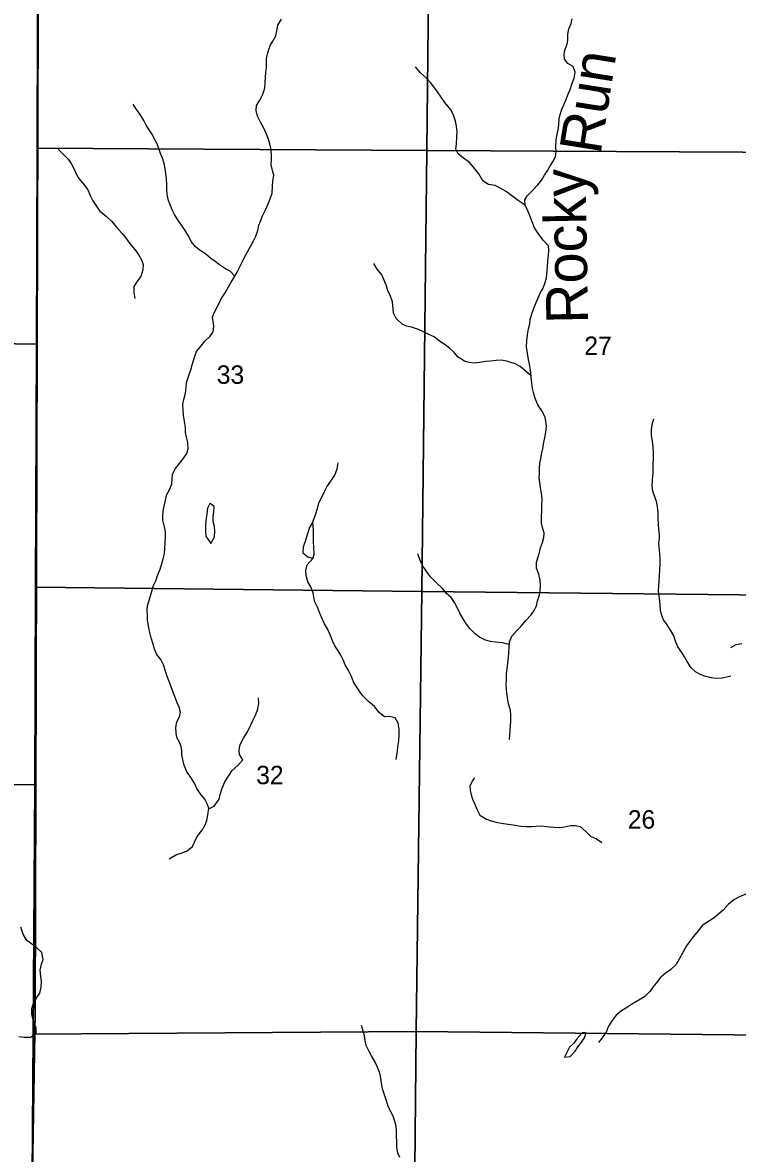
# Model space of a CAD drawing. Extents: x -10 to 158, y 8 to 33.
# Drawn here: x -7.945 to -6.322, y 10.614 to 13.18 of the extents above; entities that cross this region are included whole.
import ezdxf

# ---------------------------------------------------------------- set-up
doc = ezdxf.new("R2010")
doc.units = 0
for name, color, linetype in [('GM_X_Corporation', 7, 'Continuous'), ('GM_X_Minor_Lake', 7, 'Continuous'), ('GM_X_Minor_River', 7, 'Continuous'), ('GM_X_Minor_River_Text', 7, 'Continuous'), ('GM_X_Section_Text', 7, 'Continuous')]:
    doc.layers.add(name, color=color, linetype=linetype)

msp = doc.modelspace()

# ---------------------------------------------------------------- linework, layer by layer
at = {"layer": 'GM_X_Corporation'}
for points in [[(-7.9061, 15.1217), (-9.5644, 15.1217), (-9.5644, 9.4643), (-9.3995, 9.4613), (-9.0726, 9.4561), (-8.6489, 9.4603), (-8.2177, 9.4548), (-7.9405, 9.4552), (-7.9277, 10.2365), (-7.9276, 10.245), (-7.9163, 10.9333), (-7.9163, 10.9342), (-7.9089, 13.4536), (-7.9044, 14.3264), (-7.9061, 14.9432), (-7.9061, 14.9456)], [(-7.9093, 13.8977), (-7.016, 13.8932), (-7.0267, 12.8896), (-7.912, 12.8954), (-7.9104, 13.468)], [(-7.016, 13.8932), (-6.0166, 13.8862), (-6.0224, 12.8846), (-7.0267, 12.8896)], [(-7.9104, 13.468), (-7.912, 12.8954), (-7.9134, 12.4505), (-8.922, 12.4664), (-8.9211, 13.4645)], [(-7.0267, 12.8896), (-7.0382, 11.889), (-7.9152, 11.8987), (-7.9134, 12.4505), (-7.912, 12.8954)], [(-6.0224, 12.8846), (-6.0285, 11.878), (-7.0382, 11.889), (-7.0267, 12.8896)], [(-7.9134, 12.4505), (-7.9152, 11.8987), (-7.9172, 11.45), (-8.9234, 11.4538), (-8.922, 12.4664)], [(-7.0382, 11.889), (-7.0512, 10.8902), (-7.9205, 10.8845), (-7.9172, 11.45), (-7.9152, 11.8987)], [(-6.0285, 11.878), (-6.04, 10.88), (-7.0512, 10.8902), (-7.0382, 11.889)], [(-7.9172, 11.45), (-7.9205, 10.8845), (-7.9238, 10.4498), (-8.9307, 10.4584), (-8.9234, 11.4538)], [(-7.0512, 10.8902), (-7.0611, 9.881), (-7.9279, 9.893), (-7.9238, 10.4498), (-7.9205, 10.8845)], [(-6.04, 10.88), (-6.0536, 9.8669), (-7.0611, 9.881), (-7.0512, 10.8902)]]:
    msp.add_lwpolyline(points, close=True, dxfattribs=at)
msp.add_lwpolyline([(-3.9824, 15.1217), (-7.9061, 15.1217), (-7.9061, 14.9456), (-7.9061, 14.9432), (-7.9044, 14.3264), (-7.9089, 13.4536), (-7.9163, 10.9342), (-7.9163, 10.9333), (-7.9276, 10.245), (-7.9277, 10.2365), (-7.9405, 9.4552), (-7.9359, 8.9497), (-7.8105, 8.9446), (-6.576, 8.9279), (-5.6716, 8.9116)], dxfattribs=at)
at = {"layer": 'GM_X_Minor_Lake'}
for points in [[(-7.5158, 12.086), (-7.5194, 12.0884), (-7.525, 12.0782), (-7.5267, 12.0641), (-7.5289, 12.0508), (-7.5296, 12.0375), (-7.5295, 12.0247), (-7.5287, 12.0144), (-7.5176, 11.9982)], [(-7.5176, 11.9982), (-7.509, 12.013), (-7.5083, 12.0259), (-7.5091, 12.0365), (-7.5122, 12.0468), (-7.5123, 12.0566), (-7.5105, 12.0695), (-7.5098, 12.082), (-7.5158, 12.086)], [(-7.2856, 12.0471), (-7.2933, 12.0343), (-7.2997, 12.0155), (-7.3042, 12.0003), (-7.3079, 11.99), (-7.3085, 11.9768), (-7.2971, 11.9677), (-7.2854, 11.9636)], [(-7.2854, 11.9636), (-7.2824, 11.9739), (-7.2836, 11.9891), (-7.2845, 12.0027), (-7.2846, 12.016), (-7.2843, 12.0277), (-7.2847, 12.0372), (-7.2856, 12.0471)], [(-6.7144, 10.8323), (-6.7015, 10.8337), (-6.6899, 10.846), (-6.6836, 10.8559), (-6.6754, 10.8659), (-6.6691, 10.8758), (-6.6651, 10.8877), (-6.672, 10.8873)], [(-6.672, 10.8873), (-6.6745, 10.8872), (-6.6857, 10.8741), (-6.6928, 10.8641), (-6.7029, 10.8545), (-6.7144, 10.8323)]]:
    msp.add_lwpolyline(points, dxfattribs=at)
at = {"layer": 'GM_X_Minor_River'}
for points in [[(-7.519, 12.4685), (-7.5122, 12.4784), (-7.5104, 12.4913), (-7.5117, 12.5019), (-7.5136, 12.5113), (-7.5095, 12.5212), (-7.5043, 12.5315), (-7.498, 12.5456), (-7.492, 12.5551), (-7.4845, 12.5669), (-7.477, 12.5806), (-7.471, 12.5913), (-7.4628, 12.6042), (-7.4579, 12.6137), (-7.4523, 12.624), (-7.4479, 12.6335), (-7.4415, 12.6464), (-7.4344, 12.6598), (-7.4262, 12.6731), (-7.4206, 12.6849), (-7.4154, 12.6952), (-7.4109, 12.7085), (-7.408, 12.7202), (-7.4043, 12.7297), (-7.399, 12.7427), (-7.3931, 12.7552), (-7.3871, 12.7689), (-7.3827, 12.7799), (-7.3782, 12.7932), (-7.3776, 12.8092), (-7.3769, 12.8202), (-7.3743, 12.8335), (-7.3774, 12.8444), (-7.3802, 12.8573), (-7.3795, 12.8698), (-7.3796, 12.8805), (-7.3812, 12.8949), (-7.3831, 12.9047), (-7.3866, 12.9153), (-7.3912, 12.9267), (-7.397, 12.9403), (-7.4043, 12.9539), (-7.4112, 12.9675), (-7.4147, 12.9804), (-7.4133, 12.9917), (-7.4062, 13.0043), (-7.3991, 13.0176), (-7.3946, 13.0313), (-7.3936, 13.0435), (-7.3929, 13.0564), (-7.3922, 13.0658), (-7.3908, 13.0784), (-7.3912, 13.089), (-7.3906, 13.0988), (-7.3869, 13.1148), (-7.3828, 13.1281), (-7.3768, 13.1376), (-7.3697, 13.1502), (-7.3675, 13.1616), (-7.365, 13.1745), (-7.3567, 13.1878)], [(-6.8035, 12.7658), (-6.8047, 12.7776), (-6.7988, 12.7871), (-6.7871, 12.7989), (-6.7747, 12.8119), (-6.7657, 12.8233), (-6.7597, 12.834), (-6.7519, 12.8451), (-6.7466, 12.8546), (-6.7399, 12.8652), (-6.735, 12.8755), (-6.7332, 12.8876), (-6.7337, 12.899), (-6.7334, 12.9138), (-6.7312, 12.926), (-6.7283, 12.9404), (-6.7272, 12.9506), (-6.7262, 12.9617), (-6.7244, 12.9715), (-6.7203, 12.9837), (-6.7162, 12.9932), (-6.711, 13.0038), (-6.7058, 13.0175), (-6.7017, 13.0282), (-6.6976, 13.0403), (-6.6924, 13.054), (-6.6898, 13.0673), (-6.6948, 13.0806), (-6.707, 13.0869), (-6.7143, 13.0971), (-6.7151, 13.1074), (-6.7136, 13.1176), (-6.7081, 13.1309), (-6.707, 13.1404), (-6.7071, 13.1529), (-6.7045, 13.1662), (-6.6993, 13.178), (-6.6967, 13.1886)], [(-6.8035, 12.7658), (-6.8195, 12.7764), (-6.8343, 12.7876), (-6.8484, 12.7974), (-6.859, 12.8038), (-6.8716, 12.8102), (-6.8871, 12.8123), (-6.9, 12.8213), (-6.9085, 12.8365), (-6.9207, 12.8516), (-6.931, 12.8636), (-6.9435, 12.8726), (-6.9561, 12.8824), (-6.9607, 12.893), (-6.9597, 12.9044), (-6.9586, 12.9211), (-6.9583, 12.9321), (-6.9596, 12.945), (-6.9619, 12.9567), (-6.9673, 12.9722), (-6.9723, 12.9824), (-6.9857, 12.9987), (-7.0025, 13.0228), (-7.0109, 13.0342), (-7.0189, 13.044), (-7.0277, 13.0542), (-7.041, 13.0662), (-7.0525, 13.0794)], [(-7.4626, 12.6045), (-7.4727, 12.6155), (-7.486, 12.6226), (-7.4974, 12.6305), (-7.5073, 12.6381), (-7.5176, 12.6444), (-7.529, 12.6546), (-7.5423, 12.6636), (-7.5522, 12.6715), (-7.5621, 12.6836), (-7.5679, 12.6964), (-7.5771, 12.7104), (-7.5843, 12.7206), (-7.5939, 12.7346), (-7.6, 12.7444), (-7.605, 12.755), (-7.6089, 12.7652), (-7.6135, 12.7762), (-7.6166, 12.7898), (-7.6171, 12.8038), (-7.6171, 12.8137), (-7.618, 12.8255), (-7.6192, 12.8372), (-7.6208, 12.8478), (-7.6235, 12.8603), (-7.6274, 12.872), (-7.6316, 12.883), (-7.6351, 12.894), (-7.639, 12.9046), (-7.6451, 12.9152), (-7.6497, 12.925), (-7.6574, 12.9367), (-7.6643, 12.9469), (-7.6696, 12.9579), (-7.6777, 12.9718), (-7.688, 12.9851), (-7.6934, 12.9949)], [(-7.8641, 12.8929), (-7.8526, 12.8816), (-7.8412, 12.8699), (-7.8347, 12.8601), (-7.8282, 12.8488), (-7.8228, 12.8367), (-7.8174, 12.8261), (-7.8045, 12.811), (-7.7968, 12.8008), (-7.7903, 12.786), (-7.7849, 12.7758), (-7.7761, 12.7619), (-7.7692, 12.752), (-7.7548, 12.7404), (-7.7426, 12.7295), (-7.7304, 12.7151), (-7.7197, 12.7023), (-7.7109, 12.6921), (-7.7021, 12.6793), (-7.6899, 12.6653), (-7.6815, 12.6536), (-7.675, 12.6419), (-7.6711, 12.6313), (-7.6714, 12.6192), (-7.6766, 12.604), (-7.6841, 12.5941), (-7.6923, 12.5811), (-7.6919, 12.5675), (-7.6899, 12.5542)], [(-6.8391, 11.5531), (-6.8376, 11.5744), (-6.8369, 11.5839), (-6.8362, 11.5941), (-6.8359, 11.6089), (-6.8371, 11.6195), (-6.8418, 11.6339), (-6.843, 11.6434), (-6.845, 11.6581), (-6.8462, 11.6676), (-6.8466, 11.6782), (-6.8463, 11.6885), (-6.8457, 11.7029), (-6.8446, 11.7131), (-6.8428, 11.7253), (-6.8417, 11.7389), (-6.8407, 11.7499), (-6.84, 11.7617), (-6.8394, 11.7746), (-6.8341, 11.7872), (-6.8229, 11.8001), (-6.8135, 11.8097), (-6.8018, 11.823), (-6.7898, 11.8356), (-6.7831, 11.8459), (-6.7782, 11.8562), (-6.7753, 11.8676), (-6.772, 11.8782), (-6.7698, 11.8892), (-6.7691, 11.9032), (-6.7692, 11.9142), (-6.7727, 11.9283), (-6.7777, 11.9415), (-6.7778, 11.9544), (-6.7748, 11.965), (-6.7711, 11.9772), (-6.7689, 11.9878), (-6.7645, 12.0004), (-6.7615, 12.0114), (-6.7605, 12.0216), (-6.7643, 12.0345), (-6.7667, 12.0443), (-6.7664, 12.0572), (-6.7661, 12.0724), (-6.7655, 12.0849), (-6.7648, 12.0997), (-6.7668, 12.1115), (-6.7688, 12.1251), (-6.7704, 12.1365), (-6.7716, 12.146), (-6.7709, 12.1573), (-6.771, 12.1687), (-6.7703, 12.1809), (-6.7677, 12.1911), (-6.7655, 12.2036), (-6.7637, 12.2131), (-6.7619, 12.2238), (-6.7593, 12.2374), (-6.7568, 12.2507), (-6.755, 12.264), (-6.7566, 12.275), (-6.7581, 12.2845), (-6.7654, 12.2988), (-6.775, 12.3128), (-6.7808, 12.3268), (-6.7847, 12.3404), (-6.7866, 12.3499), (-6.7882, 12.362), (-6.7898, 12.3749), (-6.7906, 12.3851), (-6.7922, 12.3954), (-6.7938, 12.4052), (-6.7958, 12.4158), (-6.7985, 12.4298), (-6.8005, 12.4442), (-6.8002, 12.4583), (-6.7984, 12.4716), (-6.7959, 12.4852), (-6.7933, 12.4966), (-6.7919, 12.5061), (-6.7886, 12.5194), (-6.7841, 12.5316), (-6.7789, 12.5449), (-6.774, 12.5552), (-6.7692, 12.5658), (-6.7636, 12.5757), (-6.7591, 12.5882), (-6.7554, 12.6008), (-6.7537, 12.6163), (-6.7526, 12.6274), (-6.7519, 12.6387), (-6.7505, 12.6524), (-6.7498, 12.6626), (-6.751, 12.6733), (-6.7625, 12.6861), (-6.7736, 12.7008), (-6.7824, 12.7144), (-6.7877, 12.728), (-6.792, 12.7397), (-6.7974, 12.7526), (-6.8035, 12.7658)], [(-6.7901, 12.3785), (-6.8153, 12.3998), (-6.8264, 12.4054), (-6.8358, 12.4087), (-6.8453, 12.4117), (-6.8582, 12.4139), (-6.8696, 12.4131), (-6.882, 12.4119), (-6.8926, 12.411), (-6.9074, 12.4083), (-6.9191, 12.4071), (-6.9308, 12.4085), (-6.9415, 12.4119), (-6.9559, 12.4209), (-6.9647, 12.4311), (-6.975, 12.4401), (-6.9856, 12.4491), (-6.9982, 12.4574), (-7.01, 12.4672), (-7.0225, 12.4724), (-7.0331, 12.4773), (-7.046, 12.4832), (-7.0616, 12.4885), (-7.073, 12.4914), (-7.0832, 12.4955), (-7.0969, 12.5083), (-7.1027, 12.5208), (-7.1031, 12.5307), (-7.1048, 12.5466), (-7.1105, 12.5613), (-7.1151, 12.5715), (-7.1182, 12.5825), (-7.1244, 12.5973), (-7.1294, 12.6079), (-7.1397, 12.6207), (-7.1474, 12.6332)], [(-7.6122, 11.2825), (-7.5951, 11.2923), (-7.5846, 11.2954), (-7.571, 11.3), (-7.5593, 11.3103), (-7.5541, 11.3198), (-7.5481, 11.3328), (-7.5369, 11.3469), (-7.5305, 11.3594), (-7.5264, 11.3689), (-7.5239, 11.3822), (-7.5221, 11.397), (-7.5259, 11.4069), (-7.5313, 11.4174), (-7.5412, 11.4307), (-7.5489, 11.442), (-7.5543, 11.4537), (-7.5631, 11.4666), (-7.5726, 11.4813), (-7.578, 11.4945), (-7.58, 11.504), (-7.5831, 11.518), (-7.5832, 11.5275), (-7.5844, 11.537), (-7.5886, 11.5472), (-7.5943, 11.5574), (-7.5963, 11.5676), (-7.5968, 11.5805), (-7.5946, 11.5934), (-7.5886, 11.6048), (-7.5864, 11.6147), (-7.5895, 11.6264), (-7.5934, 11.6366), (-7.5988, 11.6503), (-7.6034, 11.662), (-7.6084, 11.6748), (-7.6123, 11.6847), (-7.6165, 11.696), (-7.62, 11.7078), (-7.625, 11.7225), (-7.6312, 11.7346), (-7.6396, 11.7459), (-7.645, 11.7577), (-7.6492, 11.7717), (-7.6531, 11.7834), (-7.6566, 11.7989), (-7.6586, 11.8107), (-7.6609, 11.8236), (-7.6614, 11.8342), (-7.6618, 11.8463), (-7.6608, 11.8562), (-7.6578, 11.8661), (-7.6549, 11.8767), (-7.6519, 11.887), (-7.6482, 11.901), (-7.6415, 11.9143), (-7.6382, 11.925), (-7.6326, 11.9398), (-7.6289, 11.9527), (-7.6256, 11.9634), (-7.6223, 11.9751), (-7.6216, 11.9858), (-7.6209, 11.9998), (-7.6199, 12.0131), (-7.62, 12.0248), (-7.6223, 12.0354), (-7.6262, 12.0506), (-7.6267, 12.0631), (-7.6248, 12.0756), (-7.6197, 12.0992), (-7.6171, 12.1094), (-7.6115, 12.1193), (-7.606, 12.1334), (-7.6053, 12.1448), (-7.6046, 12.1554), (-7.5975, 12.1683), (-7.5896, 12.1786), (-7.5784, 12.1923), (-7.572, 12.2019), (-7.5687, 12.2133), (-7.5695, 12.2273), (-7.5723, 12.239), (-7.5746, 12.2496), (-7.5751, 12.261), (-7.5774, 12.2747), (-7.5794, 12.2891), (-7.5803, 12.3004), (-7.5807, 12.3141), (-7.5789, 12.3243), (-7.5752, 12.3388), (-7.5734, 12.3509), (-7.5724, 12.3634), (-7.5672, 12.379), (-7.5631, 12.3919), (-7.5598, 12.4033), (-7.5568, 12.4128), (-7.5535, 12.4231), (-7.5498, 12.4334), (-7.5396, 12.4467), (-7.531, 12.4574), (-7.519, 12.4685)], [(-6.3363, 11.6965), (-6.343, 11.6955), (-6.3566, 11.6924), (-6.3706, 11.6911), (-6.3816, 11.693), (-6.3937, 11.6963), (-6.4059, 11.7008), (-6.4169, 11.7064), (-6.4268, 11.7154), (-6.4356, 11.7298), (-6.4421, 11.7404), (-6.4482, 11.7506), (-6.457, 11.763), (-6.462, 11.7763), (-6.4663, 11.788), (-6.474, 11.8008), (-6.4812, 11.8133), (-6.4896, 11.8246), (-6.4943, 11.8364), (-6.4962, 11.8462), (-6.4971, 11.8576), (-6.4979, 11.8678), (-6.4995, 11.8784), (-6.5011, 11.8898), (-6.5004, 11.9016), (-6.4993, 11.9133), (-6.4983, 11.9239), (-6.4976, 11.9387), (-6.4973, 11.9501), (-6.4974, 11.9638), (-6.4979, 11.9732), (-6.4983, 11.9835), (-6.4999, 11.9975), (-6.4985, 12.0097), (-6.4986, 12.0191), (-6.4998, 12.0297), (-6.5006, 12.0419), (-6.5015, 12.0555), (-6.5019, 12.0684), (-6.5028, 12.0817), (-6.5055, 12.093), (-6.5094, 12.104), (-6.514, 12.1165), (-6.5156, 12.1298), (-6.5146, 12.1412), (-6.5132, 12.1575), (-6.5132, 12.1681), (-6.5129, 12.1783), (-6.5126, 12.1901), (-6.512, 12.203), (-6.5128, 12.2166), (-6.5148, 12.231), (-6.5164, 12.2428), (-6.5169, 12.2553), (-6.5151, 12.2678), (-6.5117, 12.2807)], [(-7.0963, 11.5074), (-7.0934, 11.5268), (-7.0924, 11.5367), (-7.0902, 11.55), (-7.0899, 11.5629), (-7.09, 11.5762), (-7.092, 11.5898), (-7.0989, 11.6019), (-7.1114, 11.6052), (-7.1231, 11.6048), (-7.1342, 11.6138), (-7.146, 11.6281), (-7.1593, 11.6394), (-7.1727, 11.653), (-7.1795, 11.6628), (-7.1872, 11.6738), (-7.1937, 11.6836), (-7.1976, 11.6957), (-7.2052, 11.7112), (-7.2121, 11.7222), (-7.2164, 11.732), (-7.2221, 11.7441), (-7.2283, 11.7543), (-7.2359, 11.7656), (-7.2405, 11.7754), (-7.2455, 11.7891), (-7.2528, 11.8038), (-7.2593, 11.8155), (-7.2663, 11.8303), (-7.2705, 11.8409), (-7.2751, 11.853), (-7.2809, 11.8654), (-7.2836, 11.8757), (-7.2852, 11.8855), (-7.2902, 11.8995), (-7.2971, 11.9112), (-7.3006, 11.9252), (-7.3014, 11.9366), (-7.2989, 11.9495), (-7.2854, 11.9636), (-7.2824, 11.9739), (-7.2836, 11.9891), (-7.2845, 12.0027), (-7.2846, 12.016), (-7.2843, 12.0277), (-7.2847, 12.0372), (-7.2856, 12.0471), (-7.2796, 12.063), (-7.2748, 12.0771), (-7.2719, 12.09), (-7.2663, 12.1018), (-7.2595, 12.1159), (-7.2536, 12.1262), (-7.2446, 12.1391), (-7.2356, 12.1528), (-7.2308, 12.1673), (-7.2282, 12.1809)], [(-6.8397, 11.7687), (-6.8556, 11.7726), (-6.8708, 11.7736), (-6.8825, 11.7751), (-6.8935, 11.7781), (-6.9072, 11.7852), (-6.9171, 11.7931), (-6.9289, 11.8048), (-6.9369, 11.8146), (-6.9434, 11.8255), (-6.9518, 11.8395), (-6.958, 11.8524), (-6.9637, 11.8637), (-6.9718, 11.875), (-6.982, 11.8841), (-6.9916, 11.8954), (-7.0049, 11.9089), (-7.019, 11.9229), (-7.027, 11.9334), (-7.0366, 11.9478), (-7.0428, 11.9614), (-7.0474, 11.9743)], [(-6.3369, 11.7618), (-6.3246, 11.7684), (-6.3114, 11.7708)], [(-7.5222, 11.3956), (-7.51, 11.4017), (-7.4984, 11.4173), (-7.4958, 11.4283), (-7.4914, 11.4424), (-7.4858, 11.4568), (-7.4791, 11.4678), (-7.4689, 11.4823), (-7.4558, 11.4942), (-7.4445, 11.5068), (-7.4522, 11.5192), (-7.453, 11.5287), (-7.4504, 11.542), (-7.443, 11.5557), (-7.4344, 11.5702), (-7.4273, 11.585), (-7.422, 11.5964), (-7.415, 11.6101), (-7.4105, 11.6223), (-7.4087, 11.6344), (-7.4088, 11.6477)], [(-6.9184, 11.4659), (-6.9227, 11.4604), (-6.9294, 11.4475), (-6.9282, 11.4376), (-6.9262, 11.4278), (-6.9231, 11.4176), (-6.9185, 11.4077), (-6.9131, 11.3949), (-6.9062, 11.3816), (-6.8914, 11.3719), (-6.8808, 11.3682), (-6.8664, 11.3648), (-6.8527, 11.3626), (-6.8421, 11.3608), (-6.8308, 11.359), (-6.8137, 11.3561), (-6.8024, 11.3558), (-6.7895, 11.3555), (-6.7785, 11.3563), (-6.7664, 11.3568), (-6.755, 11.3557), (-6.7388, 11.3543), (-6.7251, 11.3536), (-6.7142, 11.3548), (-6.7006, 11.3579), (-6.69, 11.3576), (-6.6786, 11.3554), (-6.6657, 11.3445), (-6.6554, 11.3336), (-6.6417, 11.3276), (-6.6295, 11.3189)], [(-6.1966, 11.2427), (-6.2039, 11.2344), (-6.2137, 11.2313), (-6.2289, 11.2282), (-6.2421, 11.2236), (-6.2519, 11.2197), (-6.2655, 11.2158), (-6.2779, 11.2112), (-6.2912, 11.2069), (-6.3025, 11.2019), (-6.3168, 11.1958), (-6.3296, 11.1889), (-6.3424, 11.1786), (-6.3541, 11.1656), (-6.3745, 11.1479)], [(-6.3745, 11.1479), (-6.4015, 11.1307), (-6.4101, 11.1199), (-6.4183, 11.1099), (-6.4277, 11.0981), (-6.437, 11.085), (-6.4451, 11.0712), (-6.4529, 11.0556), (-6.4611, 11.0422), (-6.4731, 11.031), (-6.4858, 11.0217), (-6.4963, 11.0129), (-6.506, 11.0002), (-6.5135, 10.9906), (-6.5202, 10.981), (-6.5322, 10.9695), (-6.5458, 10.9614), (-6.5597, 10.9528), (-6.571, 10.9455), (-6.5849, 10.9373), (-6.5969, 10.9273), (-6.6062, 10.915), (-6.6144, 10.9024), (-6.6199, 10.8886), (-6.6285, 10.8756), (-6.6371, 10.8656)], [(-7.953, 10.8786), (-7.9412, 10.8772), (-7.9268, 10.8778), (-7.9137, 10.8859), (-7.9142, 10.8988), (-7.9181, 10.9094), (-7.9213, 10.9196), (-7.9237, 10.9295), (-7.9239, 10.9427), (-7.921, 10.9523), (-7.9125, 10.9672), (-7.9058, 10.9772), (-7.9025, 10.9912), (-7.9015, 11.0038), (-7.9032, 11.0148), (-7.9049, 11.0292), (-7.9021, 11.0429), (-7.898, 11.0536), (-7.9013, 11.0695), (-7.9143, 11.0815), (-7.9247, 11.0889), (-7.9354, 11.0971), (-7.9432, 11.1111), (-7.9489, 11.1272)], [(-7.0882, 10.6042), (-7.0929, 10.6141), (-7.0949, 10.6285), (-7.0954, 10.6641), (-7.0967, 10.6755), (-7.0995, 10.6861), (-7.1027, 10.6959), (-7.1093, 10.7099), (-7.1144, 10.7201), (-7.1191, 10.7352), (-7.123, 10.7469), (-7.1278, 10.7602), (-7.1298, 10.7727), (-7.1311, 10.7844), (-7.1336, 10.7958), (-7.1398, 10.8109), (-7.1441, 10.8207), (-7.1527, 10.835), (-7.1581, 10.8448), (-7.1647, 10.8588), (-7.1672, 10.8702), (-7.1688, 10.8804), (-7.1716, 10.891), (-7.1756, 10.9042)]]:
    msp.add_lwpolyline(points, dxfattribs=at)

# ---------------------------------------------------------------- texts
at = {"layer": 'GM_X_Minor_River_Text'}
for s, height, rotation, p in [('Run', 0.09469, 81.0065, (-6.6327, 12.8788)), ('Rocky', 0.09468, 91.0077, (-6.6607, 12.4972))]:
    msp.add_text(s, height=height, rotation=rotation, dxfattribs=at).set_placement(p)
at = {"layer": 'GM_X_Section_Text'}
for s, p in [('27', (-6.6693, 12.4257)), ('33', (-7.5039, 12.3602)), ('32', (-7.4143, 11.4515)), ('26', (-6.5706, 11.3507))]:
    msp.add_text(s, height=0.04186, rotation=0, dxfattribs=at).set_placement(p)

doc.saveas('drawing.dxf')
